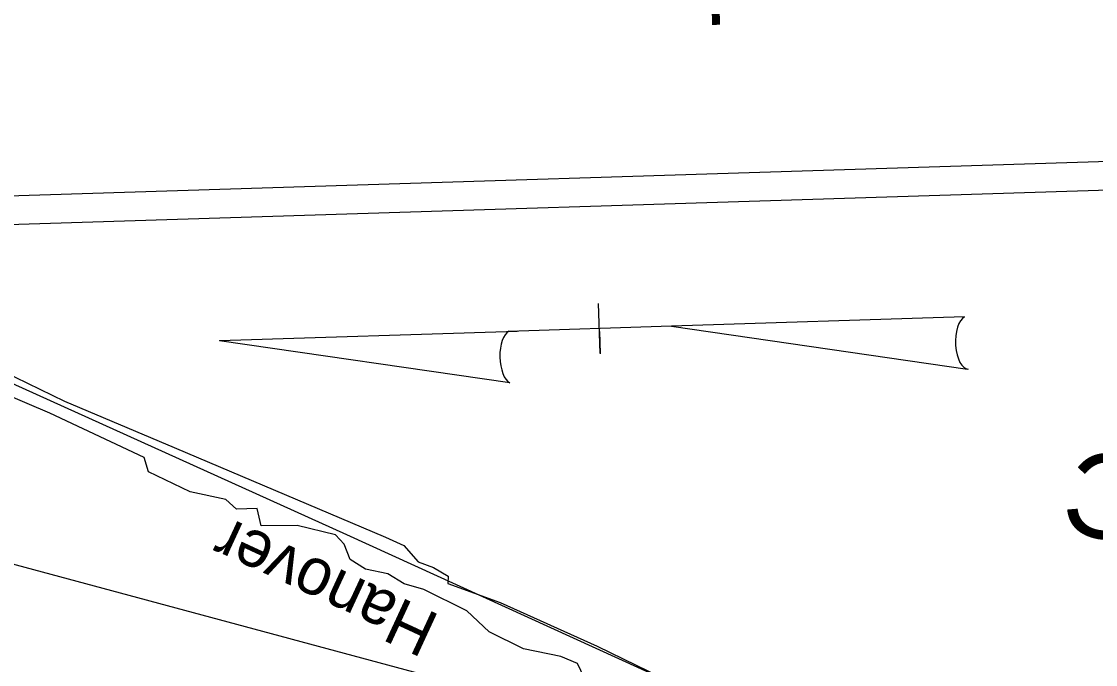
# Model space of a CAD drawing. Extents: x 2308163 to 2335412, y -96774 to 125428.
# Drawn here: x 2326033 to 2326312.3, y 123340.9 to 123508 of the extents above; entities that cross this region are included whole.
import ezdxf

# ---------------------------------------------------------------- set-up
doc = ezdxf.new("R2010")
doc.units = 0
for name, color, linetype in [('Default', 7, 'Continuous'), ('Old_Level_1', 7, 'Continuous'), ('Old_Level_19', 7, 'Continuous'), ('Old_Level_21', 7, 'Continuous'), ('Old_Level_52', 7, 'Continuous'), ('Old_Level_60', 7, 'Continuous'), ('Old_Level_63', 7, 'Continuous'), ('Prop North Arrow for Plan Sheets CELL', 7, 'Continuous'), ('Sheet Title CELL', 7, 'Continuous')]:
    doc.layers.add(name, color=color, linetype=linetype)

# ---------------------------------------------------------------- blocks, each defined once
blk = doc.blocks.new('North Arrow for Plan Sheets-E')
at = {"layer": 'Prop North Arrow for Plan Sheets CELL'}
for p, q in [((-0.1659, 0.293), (-0.0019, 1.22)), ((-0.0009, 1.22), (-0.0019, 1.22)), ((-0.0009, 1.22), (-0.0019, 1.22)), ((-0.0009, 1.22), (-0.0009, 0.264)), ((-0.0009, -0.232), (-0.0009, 0.292)), ((-0.0009, 0.264), (-0.0009, 0.291)), ((-0.0809, 0), (-0.0819, 0)), ((-0.0099, 0), (-0.0809, 0)), ((-0.0799, 0), (0.0801, 0)), ((-0.0009, -0.232), (-0.1679, -1.177)), ((0.0001, -1.173), (-0.0009, -0.232))]:
    blk.add_line(p, q, dxfattribs=at)
for centre, start_param, end_param in [((-0.0832, 0.2831), 0.216388, 2.908219), ((-0.0832, -1.1803), 0.201328, 3.141593)]:
    blk.add_ellipse(centre, major_axis=(0.0846, -0.0006), ratio=0.461098, start_param=start_param, end_param=end_param, dxfattribs=at)

msp = doc.modelspace()

# ---------------------------------------------------------------- linework, layer by layer
at = {"layer": 'Old_Level_1'}
for p, q in [((2325949.48, 123460.16), (2326443.34, 123475.72)), ((2325949.72, 123452.66), (2326443.57, 123468.22))]:
    msp.add_line(p, q, dxfattribs=at)
at = {"layer": 'Old_Level_52'}
msp.add_lwpolyline([(2326352.46, 123278.37), (2326344.49, 123279.39), (2326334.11, 123277.47), (2326314.41, 123278.3), (2326300.12, 123278.02), (2326291.22, 123283.57), (2326287.11, 123292.06), (2326280.06, 123298.67), (2326266.15, 123306.08), (2326194.23, 123339.67), (2326117.56, 123374.58), (2325996.97, 123429.09), (2325967.84, 123440.3), (2325941.49, 123450.31)], dxfattribs=at)
at = {"layer": 'Old_Level_60'}
for points in [[(2325943.78, 123451.42), (2325950.75, 123448.77), (2325974.15, 123440.27), (2325991.46, 123433.15), (2326015.22, 123423.35), (2326044.14, 123409.29), (2326072.73, 123397.29), (2326127.66, 123373.96)], [(2326179.29, 123337.5), (2326177.6, 123341.14), (2326173.26, 123342.95), (2326163.49, 123344.95), (2326154.57, 123349.39), (2326148.8, 123354.84), (2326137.6, 123360.36), (2326132.53, 123361.86), (2326128.26, 123364.49), (2326122.4, 123365.69), (2326118.44, 123368.15), (2326116.87, 123372.18), (2326114.62, 123374.57), (2326104.7, 123377), (2326095.31, 123376.92), (2326094.24, 123381.45), (2326088.92, 123381.22), (2326086.15, 123383.76), (2326076.82, 123385.72), (2326065.98, 123390.99), (2326064.88, 123394.7), (2326040.36, 123406.16), (2325988.84, 123428.14)], [(2326127.66, 123373.96), (2326132.4, 123371.8), (2326136.14, 123367.53), (2326140.13, 123366.07), (2326143.93, 123363.85), (2326143.86, 123361.92), (2326157.43, 123357.03), (2326182.68, 123345.67), (2326202.81, 123335.85), (2326223.69, 123325.46), (2326232.34, 123320.74), (2326241.56, 123317.67)]]:
    msp.add_lwpolyline(points, dxfattribs=at)
at = {"layer": 'Old_Level_63'}
msp.add_lwpolyline([(2326475.8, 123239.36), (2326422.14, 123261.61), (2325934.09, 123392.92)], dxfattribs=at)

# ---------------------------------------------------------------- block references
at = {"layer": 'Default', "xscale": 81, "yscale": 81, "rotation": 91.80479200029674}
msp.add_blockref('North Arrow for Plan Sheets-E', (2326183.26, 123428.24), dxfattribs=at)

# ---------------------------------------------------------------- texts
at = {"layer": 'Old_Level_19'}
msp.add_text('Hanover', height=12.145, rotation=155.1566, dxfattribs=at).set_placement((2326142.2, 123353.54))
at = {"layer": 'Old_Level_21'}
msp.add_text('ATLANTIC', height=21.862, rotation=164.9405, dxfattribs=at).set_placement((2326444.48, 123360.97))
at = {"layer": 'Sheet Title CELL'}
msp.add_text('TYPE OF WORK:', height=18.7501, rotation=91.8048, dxfattribs=at).set_placement((2326231.34, 123507.08))

doc.saveas('drawing.dxf')
